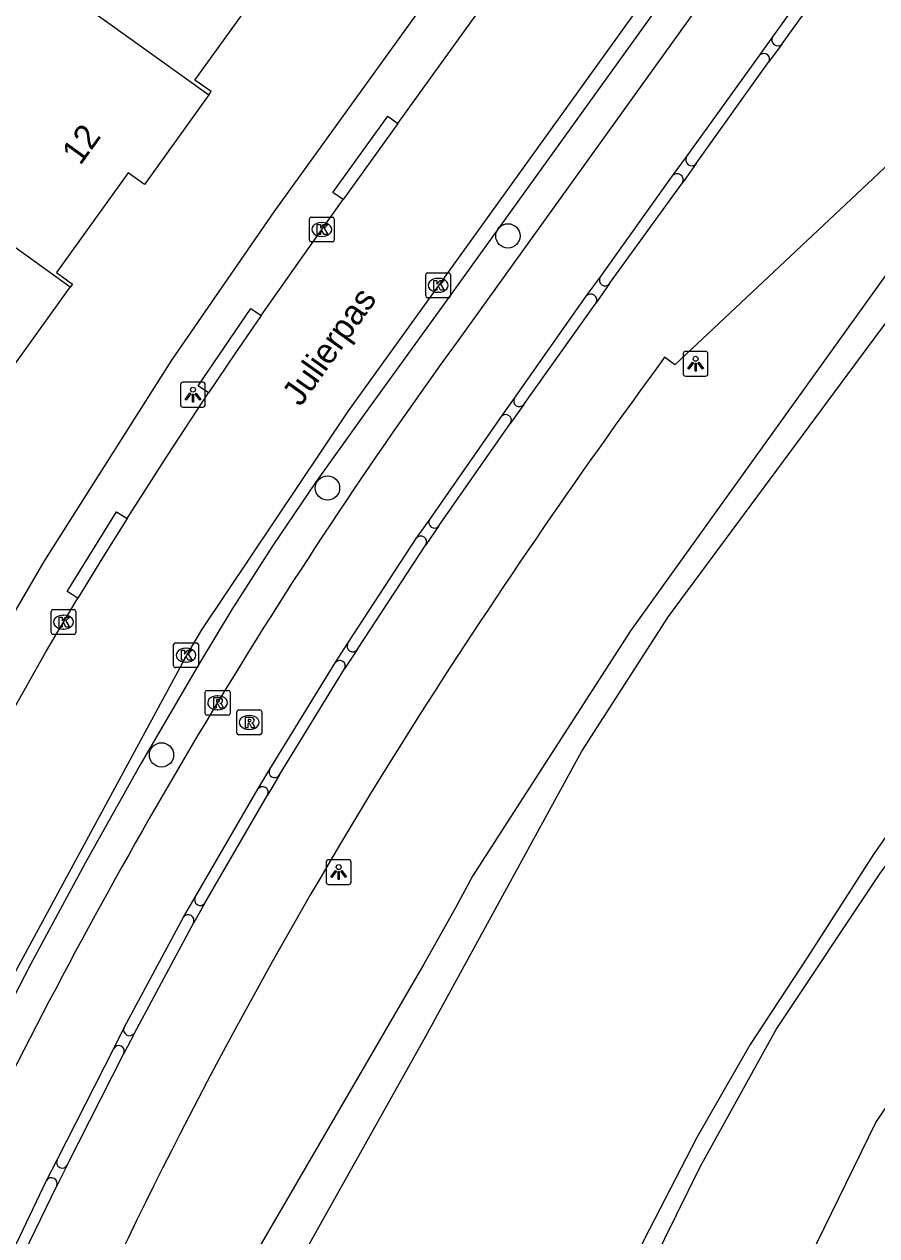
# Model space of a CAD drawing. Extents: x 158838 to 160074, y 386376 to 387776.
# Drawn here: x 159243.35 to 159277.66, y 386797.89 to 386846.63 of the extents above; entities that cross this region are included whole.
import ezdxf

# ---------------------------------------------------------------- set-up
doc = ezdxf.new("R2010")
doc.units = 0
for name, color, linetype in [('IMGEO_Berm_groen', 7, 'Continuous'), ('IMGEO_Boom', 7, 'Continuous'), ('IMGEO_Fietspad_gesloten', 7, 'Continuous'), ('IMGEO_Groenvoorziening', 7, 'Continuous'), ('IMGEO_Haag', 7, 'Continuous'), ('IMGEO_Kolk', 7, 'Continuous'), ('IMGEO_Lichtpunt', 7, 'Continuous'), ('IMGEO_Loofbos', 7, 'Continuous'), ('IMGEO_Openbare_ruimte_label', 7, 'Continuous'), ('IMGEO_OVBaan_gesloten', 7, 'Continuous'), ('IMGEO_Pand', 7, 'Continuous'), ('IMGEO_Pand_nummerreeks', 7, 'Continuous'), ('IMGEO_Rijbaan_lokaal_open', 7, 'Continuous'), ('IMGEO_Rioolput', 7, 'Continuous'), ('IMGEO_Voetpad_open', 7, 'Continuous'), ('IMGEO_Waterloop', 7, 'Continuous')]:
    doc.layers.add(name, color=color, linetype=linetype)

msp = doc.modelspace()

# ---------------------------------------------------------------- linework, layer by layer
at = {"layer": 'IMGEO_Berm_groen'}
msp.add_lwpolyline([(159295.387, 386860.749), (159267.753, 386822.227), (159261.396, 386812.36), (159260.712, 386811.091), (159259.44, 386808.818), (159251.504, 386795.194), (159240.385, 386772.855), (159239.987, 386771.45), (159240.04, 386770.482), (159240.179, 386769.522), (159240.404, 386768.578), (159240.711, 386767.659), (159241.1, 386766.77), (159241.567, 386765.92), (159242.107, 386765.115), (159242.718, 386764.361), (159243.393, 386763.665), (159243.51, 386763.556), (159246.227, 386761.743)], dxfattribs=at)
at = {"layer": 'IMGEO_Boom'}
for centre in [(159262.816, 386838.112), (159255.556, 386827.97), (159248.878, 386817.236)]:
    msp.add_circle(centre, 0.489, dxfattribs=at)
at = {"layer": 'IMGEO_Fietspad_gesloten'}
for points in [[(159289.915, 386874.409), (159260.77, 386833.848)], [(159273.477, 386846.12), (159276.398, 386850.189)], [(159272.946, 386845.362), (159273.477, 386846.12)], [(159270.006, 386841.288), (159272.946, 386845.362)], [(159269.44, 386840.528), (159270.006, 386841.288)], [(159266.538, 386836.462), (159269.44, 386840.528)], [(159265.97, 386835.682), (159266.538, 386836.462)], [(159263.08, 386831.588), (159265.97, 386835.682)], [(159262.563, 386830.847), (159263.08, 386831.588)], [(159259.672, 386826.703), (159262.563, 386830.847)], [(159259.131, 386825.94), (159259.672, 386826.703)], [(159256.371, 386821.725), (159259.131, 386825.94)], [(159255.867, 386820.937), (159256.371, 386821.725)], [(159253.231, 386816.66), (159255.867, 386820.937)], [(159252.754, 386815.852), (159253.231, 386816.66)], [(159250.234, 386811.517), (159252.754, 386815.852)], [(159249.766, 386810.71), (159250.234, 386811.517)], [(159247.374, 386806.27), (159249.766, 386810.71)], [(159246.955, 386805.428), (159247.374, 386806.27)], [(159244.68, 386800.944), (159246.955, 386805.428)], [(159244.248, 386800.111), (159244.68, 386800.944)], [(159242.073, 386795.583), (159244.248, 386800.111)]]:
    msp.add_lwpolyline(points, dxfattribs=at)
for centre, radius, start, end in [((159428.466, 386711.976), 207.304, 143.99241, 148.91485), ((159443.078, 386703.143), 224.378, 148.90963, 153.47047)]:
    msp.add_arc(centre, radius, start, end, dxfattribs=at)
at = {"layer": 'IMGEO_Groenvoorziening'}
msp.add_lwpolyline([(159246.227, 386761.743), (159247.31, 386761.41), (159248.321, 386761.304), (159249.049, 386761.409), (159249.654, 386761.53), (159250.281, 386761.789), (159250.668, 386761.999), (159250.994, 386762.252), (159251.323, 386762.46), (159251.632, 386762.697), (159251.919, 386762.96), (159251.99, 386763.033), (159270.556, 386800.667), (159273.614, 386806.196), (159277.779, 386812.449), (159305.768, 386851.337)], dxfattribs=at)
at = {"layer": 'IMGEO_Haag'}
msp.add_lwpolyline([(159273.392, 386853.651), (159260.53, 386835.762), (159256.863, 386830.685), (159255.079, 386828.194), (159253.364, 386825.663), (159251.714, 386823.086), (159250.404, 386820.929), (159248.07, 386816.93), (159245.802, 386812.886), (159243.604, 386808.803), (159241.476, 386804.683), (159240.155, 386802.033), (159239.189, 386800.003), (159238.681, 386799.182), (159238.109, 386798.417), (159237.471, 386797.706)], dxfattribs=at)
at = {"layer": 'IMGEO_Kolk'}
for p, q in [((159254.827, 386837.945), (159254.827, 386838.797)), ((159254.902, 386838.871), (159255.754, 386838.871)), ((159255.828, 386838.797), (159255.828, 386837.945)), ((159255.315, 386838.651), (159255.34, 386838.651)), ((159255.754, 386837.871), (159254.902, 386837.871)), ((159255.338, 386838.091), (159255.313, 386838.091)), ((159259.511, 386835.698), (159259.511, 386836.55)), ((159259.586, 386836.624), (159260.438, 386836.624)), ((159259.999, 386836.404), (159260.024, 386836.404)), ((159260.512, 386836.55), (159260.512, 386835.698)), ((159260.022, 386835.844), (159259.997, 386835.844)), ((159260.438, 386835.624), (159259.586, 386835.624)), ((159244.434, 386822.153), (159244.434, 386823.005)), ((159244.509, 386823.079), (159245.361, 386823.079)), ((159244.922, 386822.859), (159244.947, 386822.859)), ((159245.435, 386823.005), (159245.435, 386822.153)), ((159244.945, 386822.299), (159244.92, 386822.299)), ((159245.361, 386822.079), (159244.509, 386822.079)), ((159249.363, 386820.819), (159249.363, 386821.671)), ((159249.438, 386821.745), (159250.29, 386821.745)), ((159250.364, 386821.671), (159250.364, 386820.819)), ((159249.851, 386821.525), (159249.876, 386821.525)), ((159250.29, 386820.745), (159249.438, 386820.745)), ((159249.874, 386820.965), (159249.849, 386820.965))]:
    msp.add_line(p, q, dxfattribs=at)
for points in [[(159254.827, 386837.945), (159254.827, 386838.797)], [(159254.902, 386838.871), (159255.754, 386838.871)], [(159255.828, 386838.797), (159255.828, 386837.945)], [(159255.148, 386838.571), (159255.271, 386838.571), (159255.271, 386838.42), (159255.401, 386838.571), (159255.565, 386838.571), (159255.419, 386838.42), (159255.572, 386838.171), (159255.42, 386838.171), (159255.335, 386838.335), (159255.271, 386838.268), (159255.271, 386838.171), (159255.148, 386838.171), (159255.148, 386838.571)], [(159255.754, 386837.871), (159254.902, 386837.871)], [(159259.511, 386835.698), (159259.511, 386836.55)], [(159259.586, 386836.624), (159260.438, 386836.624)], [(159259.832, 386836.324), (159259.955, 386836.324), (159259.955, 386836.173), (159260.085, 386836.324), (159260.249, 386836.324), (159260.103, 386836.173), (159260.256, 386835.924), (159260.104, 386835.924), (159260.019, 386836.088), (159259.955, 386836.021), (159259.955, 386835.924), (159259.832, 386835.924), (159259.832, 386836.324)], [(159260.512, 386836.55), (159260.512, 386835.698)], [(159260.438, 386835.624), (159259.586, 386835.624)], [(159244.434, 386822.153), (159244.434, 386823.005)], [(159244.509, 386823.079), (159245.361, 386823.079)], [(159244.755, 386822.779), (159244.878, 386822.779), (159244.878, 386822.628), (159245.008, 386822.779), (159245.172, 386822.779), (159245.026, 386822.628), (159245.179, 386822.379), (159245.027, 386822.379), (159244.942, 386822.543), (159244.878, 386822.476), (159244.878, 386822.379), (159244.755, 386822.379), (159244.755, 386822.779)], [(159245.435, 386823.005), (159245.435, 386822.153)], [(159245.361, 386822.079), (159244.509, 386822.079)], [(159249.363, 386820.819), (159249.363, 386821.671)], [(159249.438, 386821.745), (159250.29, 386821.745)], [(159250.364, 386821.671), (159250.364, 386820.819)], [(159249.684, 386821.445), (159249.807, 386821.445), (159249.807, 386821.294), (159249.937, 386821.445), (159250.101, 386821.445), (159249.955, 386821.294), (159250.108, 386821.045), (159249.956, 386821.045), (159249.871, 386821.209), (159249.807, 386821.142), (159249.807, 386821.045), (159249.684, 386821.045), (159249.684, 386821.445)], [(159250.29, 386820.745), (159249.438, 386820.745)]]:
    msp.add_lwpolyline(points, dxfattribs=at)
for centre, start, end in [((159254.904, 386838.795), 91.552, 178.448), ((159254.904, 386838.795), 91.552, 178.448), ((159255.752, 386838.795), 1.552, 88.448), ((159255.752, 386838.795), 1.552, 88.448), ((159254.904, 386837.947), 181.552, 268.448), ((159254.904, 386837.947), 181.552, 268.448), ((159255.752, 386837.947), 271.552, 358.448), ((159255.752, 386837.947), 271.552, 358.448), ((159259.588, 386836.548), 91.552, 178.448), ((159259.588, 386836.548), 91.552, 178.448), ((159260.436, 386836.548), 1.552, 88.448), ((159260.436, 386836.548), 1.552, 88.448), ((159259.588, 386835.7), 181.552, 268.448), ((159259.588, 386835.7), 181.552, 268.448), ((159260.436, 386835.7), 271.552, 358.448), ((159260.436, 386835.7), 271.552, 358.448), ((159244.511, 386823.003), 91.552, 178.448), ((159244.511, 386823.003), 91.552, 178.448), ((159245.359, 386823.003), 1.552, 88.448), ((159245.359, 386823.003), 1.552, 88.448), ((159244.511, 386822.155), 181.552, 268.448), ((159244.511, 386822.155), 181.552, 268.448), ((159245.359, 386822.155), 271.552, 358.448), ((159245.359, 386822.155), 271.552, 358.448), ((159249.44, 386821.669), 91.552, 178.448), ((159249.44, 386821.669), 91.552, 178.448), ((159250.288, 386821.669), 1.552, 88.448), ((159250.288, 386821.669), 1.552, 88.448), ((159249.44, 386820.821), 181.552, 268.448), ((159249.44, 386820.821), 181.552, 268.448), ((159250.288, 386820.821), 271.552, 358.448), ((159250.288, 386820.821), 271.552, 358.448)]:
    msp.add_arc(centre, 0.0765, start, end, dxfattribs=at)
for centre, major_axis, ratio, start_param, end_param in [((159255.314, 386838.371), (-0.387, 0.002), 0.722429, 4.712389, 7.853982), ((159255.339, 386838.371), (-0.39, 0.002), 0.717154, 1.570796, 4.712389), ((159259.998, 386836.124), (-0.387, 0.002), 0.722429, 4.712389, 7.853982), ((159260.023, 386836.124), (-0.39, 0.002), 0.717154, 1.570796, 4.712389), ((159244.921, 386822.579), (-0.387, 0.002), 0.722429, 4.712389, 7.853982), ((159244.946, 386822.579), (-0.39, 0.002), 0.717154, 1.570796, 4.712389), ((159249.85, 386821.245), (-0.387, 0.002), 0.722429, 4.712389, 7.853982), ((159249.875, 386821.245), (-0.39, 0.002), 0.717154, 1.570796, 4.712389)]:
    msp.add_ellipse(centre, major_axis=major_axis, ratio=ratio, start_param=start_param, end_param=end_param, dxfattribs=at)
at = {"layer": 'IMGEO_Lichtpunt'}
for p, q in [((159269.871, 386833.372), (159269.871, 386832.565)), ((159269.871, 386833.372), (159269.871, 386832.565)), ((159270.773, 386833.467), (159269.965, 386833.467)), ((159270.773, 386833.467), (159269.965, 386833.467)), ((159270.867, 386832.565), (159270.867, 386833.372)), ((159270.867, 386832.565), (159270.867, 386833.372)), ((159269.965, 386832.471), (159270.773, 386832.471)), ((159269.965, 386832.471), (159270.773, 386832.471)), ((159249.644, 386832.129), (159249.644, 386831.322)), ((159249.644, 386832.129), (159249.644, 386831.322)), ((159250.546, 386832.224), (159249.738, 386832.224)), ((159250.546, 386832.224), (159249.738, 386832.224)), ((159250.64, 386831.322), (159250.64, 386832.129)), ((159250.64, 386831.322), (159250.64, 386832.129)), ((159249.738, 386831.228), (159250.546, 386831.228)), ((159249.738, 386831.228), (159250.546, 386831.228)), ((159255.509, 386812.926), (159255.509, 386812.119)), ((159255.509, 386812.926), (159255.509, 386812.119)), ((159256.411, 386813.021), (159255.603, 386813.021)), ((159256.411, 386813.021), (159255.603, 386813.021)), ((159256.505, 386812.119), (159256.505, 386812.926)), ((159256.505, 386812.119), (159256.505, 386812.926)), ((159255.603, 386812.025), (159256.411, 386812.025)), ((159255.603, 386812.025), (159256.411, 386812.025))]:
    msp.add_line(p, q, dxfattribs=at)
for points in [[(159270.245, 386833.036), (159270.284, 386833.008), (159270.096, 386832.746), (159270.058, 386832.773), (159270.245, 386833.036)], [(159270.347, 386832.988), (159270.394, 386832.988), (159270.394, 386832.666), (159270.347, 386832.666), (159270.347, 386832.988)], [(159270.457, 386833.008), (159270.495, 386833.035), (159270.682, 386832.773), (159270.643, 386832.745), (159270.457, 386833.008)], [(159250.018, 386831.793), (159250.057, 386831.765), (159249.869, 386831.503), (159249.831, 386831.53), (159250.018, 386831.793)], [(159250.12, 386831.745), (159250.167, 386831.745), (159250.167, 386831.423), (159250.12, 386831.423), (159250.12, 386831.745)], [(159250.23, 386831.765), (159250.268, 386831.792), (159250.455, 386831.53), (159250.416, 386831.502), (159250.23, 386831.765)], [(159255.883, 386812.59), (159255.922, 386812.562), (159255.734, 386812.3), (159255.696, 386812.327), (159255.883, 386812.59)], [(159255.985, 386812.542), (159256.032, 386812.542), (159256.032, 386812.22), (159255.985, 386812.22), (159255.985, 386812.542)], [(159256.095, 386812.562), (159256.133, 386812.589), (159256.32, 386812.327), (159256.281, 386812.299), (159256.095, 386812.562)]]:
    msp.add_lwpolyline(points, dxfattribs=at)
for centre in [(159270.37, 386833.17), (159250.143, 386831.927), (159256.008, 386812.724)]:
    msp.add_circle(centre, 0.0994, dxfattribs=at)
for centre, start, end in [((159269.965, 386833.372), 90, 180), ((159269.965, 386833.372), 90, 180), ((159270.773, 386833.372), 0, 90), ((159270.773, 386833.372), 0, 90), ((159269.965, 386832.565), 180, 270), ((159269.965, 386832.565), 180, 270), ((159270.773, 386832.565), 270, 0), ((159270.773, 386832.565), 270, 360), ((159249.738, 386832.129), 90, 180), ((159249.738, 386832.129), 90, 180), ((159250.546, 386832.129), 0, 90), ((159250.546, 386832.129), 0, 90), ((159249.738, 386831.322), 180, 270), ((159249.738, 386831.322), 180, 270), ((159250.546, 386831.322), 270, 0), ((159250.546, 386831.322), 270, 360), ((159255.603, 386812.926), 90, 180), ((159255.603, 386812.926), 90, 180), ((159256.411, 386812.926), 0, 90), ((159256.411, 386812.926), 0, 90), ((159255.603, 386812.119), 180, 270), ((159255.603, 386812.119), 180, 270), ((159256.411, 386812.119), 270, 0), ((159256.411, 386812.119), 270, 360)]:
    msp.add_arc(centre, 0.0946, start, end, dxfattribs=at)
at = {"layer": 'IMGEO_Loofbos'}
msp.add_lwpolyline([(159253.846, 386749.624), (159253.963, 386750), (159257.448, 386761.205), (159277.624, 386802.456), (159300.846, 386836.608), (159308.987, 386845.652), (159313.324, 386845.108), (159309.692, 386855.626)], dxfattribs=at)
at = {"layer": 'IMGEO_OVBaan_gesloten'}
for points in [[(159295.549, 386869.585), (159292.478, 386862.818), (159289.882, 386857.012), (159279.508, 386842.292), (159269.535, 386832.931), (159269.123, 386833.233)], [(159273.85, 386845.844), (159276.783, 386849.924)], [(159273.85, 386845.844), (159273.308, 386845.095)], [(159270.387, 386841.02), (159273.308, 386845.095)], [(159270.387, 386841.02), (159269.839, 386840.252)], [(159266.905, 386836.191), (159269.839, 386840.252)], [(159266.905, 386836.191), (159266.365, 386835.415)], [(159263.456, 386831.331), (159266.365, 386835.415)], [(159263.456, 386831.331), (159262.923, 386830.576)], [(159260.033, 386826.444), (159262.923, 386830.576)], [(159260.033, 386826.444), (159259.51, 386825.68)], [(159256.76, 386821.485), (159259.51, 386825.68)], [(159256.76, 386821.485), (159256.246, 386820.694)], [(159253.627, 386816.43), (159256.246, 386820.694)], [(159253.627, 386816.43), (159253.143, 386815.617)], [(159250.623, 386811.274), (159253.143, 386815.617)], [(159250.623, 386811.274), (159250.159, 386810.469)], [(159247.79, 386806.047), (159250.159, 386810.469)], [(159247.79, 386806.047), (159247.36, 386805.224)], [(159245.086, 386800.74), (159247.36, 386805.224)], [(159245.086, 386800.74), (159244.661, 386799.903)], [(159242.481, 386795.398), (159244.661, 386799.903)]]:
    msp.add_lwpolyline(points, dxfattribs=at)
for centre, radius, start, end in [((159485.462, 386674.364), 268.406, 143.70823, 147.55786), ((159439.59, 386704.553), 213.5, 147.79118, 154.52356)]:
    msp.add_arc(centre, radius, start, end, dxfattribs=at)
at = {"layer": 'IMGEO_Pand'}
for points in [[(159250.785, 386843.792), (159250.873, 386843.914), (159250.224, 386844.381), (159253.121, 386848.404), (159253.77, 386847.937), (159256.368, 386851.544)], [(159244.539, 386848.455), (159244.452, 386848.333), (159250.785, 386843.792)], [(159250.785, 386843.792), (159248.187, 386840.183), (159247.538, 386840.651), (159244.647, 386836.636), (159245.296, 386836.169), (159245.208, 386836.047)], [(159245.208, 386836.047), (159238.885, 386840.592), (159238.973, 386840.714), (159235.399, 386843.28)], [(159239.613, 386828.276), (159239.701, 386828.399), (159239.052, 386828.867), (159241.96, 386832.905), (159242.609, 386832.438), (159245.208, 386836.047)]]:
    msp.add_lwpolyline(points, dxfattribs=at)
at = {"layer": 'IMGEO_Rijbaan_lokaal_open'}
for points in [[(159231.305, 386794.999), (159233.189, 386795.661), (159234.033, 386796.005), (159234.842, 386796.423), (159235.611, 386796.912), (159236.333, 386797.468), (159237.003, 386798.086), (159237.614, 386798.761), (159238.163, 386799.488), (159238.645, 386800.261), (159238.66, 386800.288), (159239.618, 386802.301), (159249.891, 386821.241), (159250.502, 386822.26), (159256.377, 386831.036), (159260.043, 386836.113), (159272.905, 386854.001), (159286.185, 386872.449), (159287.428, 386874.189), (159288.379, 386875.519)], [(159258.389, 386842.63), (159261.71, 386847.24)], [(159258.389, 386842.63), (159256.182, 386839.57)], [(159252.89, 386834.913), (159254.612, 386837.365), (159255.325, 386838.371), (159256.182, 386839.57)], [(159252.89, 386834.913), (159251.827, 386833.362), (159250.77, 386831.801)], [(159247.494, 386826.746), (159249.115, 386829.285), (159250.77, 386831.801)], [(159247.494, 386826.746), (159246.504, 386825.164), (159245.506, 386823.542)], [(159242.728, 386818.731), (159244.208, 386821.349), (159244.932, 386822.579), (159245.506, 386823.542)]]:
    msp.add_lwpolyline(points, dxfattribs=at)
at = {"layer": 'IMGEO_Rioolput'}
for p, q in [((159250.636, 386818.905), (159250.636, 386819.757)), ((159250.711, 386819.831), (159251.563, 386819.831)), ((159251.637, 386819.757), (159251.637, 386818.905)), ((159251.124, 386819.611), (159251.149, 386819.611)), ((159251.563, 386818.831), (159250.711, 386818.831)), ((159251.147, 386819.051), (159251.122, 386819.051)), ((159251.908, 386818.116), (159251.908, 386818.968)), ((159251.983, 386819.042), (159252.835, 386819.042)), ((159252.396, 386818.822), (159252.421, 386818.822)), ((159252.909, 386818.968), (159252.909, 386818.116)), ((159252.419, 386818.262), (159252.394, 386818.262)), ((159252.835, 386818.042), (159251.983, 386818.042))]:
    msp.add_line(p, q, dxfattribs=at)
for points in [[(159250.636, 386818.905), (159250.636, 386819.757)], [(159250.711, 386819.831), (159251.563, 386819.831)], [(159251.637, 386819.757), (159251.637, 386818.905)], [(159251.225, 386819.529), (159250.973, 386819.531), (159250.973, 386819.131)], [(159250.973, 386819.131), (159251.097, 386819.131), (159251.097, 386819.293), (159251.108, 386819.293)], [(159251.151, 386819.45), (159251.097, 386819.45), (159251.097, 386819.369)], [(159251.097, 386819.369), (159251.149, 386819.369)], [(159251.155, 386819.264), (159251.226, 386819.131), (159251.366, 386819.131), (159251.301, 386819.257)], [(159251.563, 386818.831), (159250.711, 386818.831)], [(159251.908, 386818.116), (159251.908, 386818.968)], [(159251.983, 386819.042), (159252.835, 386819.042)], [(159252.497, 386818.74), (159252.245, 386818.742), (159252.245, 386818.342)], [(159252.909, 386818.968), (159252.909, 386818.116)], [(159252.245, 386818.342), (159252.369, 386818.342), (159252.369, 386818.504), (159252.38, 386818.504)], [(159252.423, 386818.661), (159252.369, 386818.661), (159252.369, 386818.58)], [(159252.369, 386818.58), (159252.421, 386818.58)], [(159252.427, 386818.475), (159252.498, 386818.342), (159252.638, 386818.342), (159252.573, 386818.468)], [(159252.835, 386818.042), (159251.983, 386818.042)]]:
    msp.add_lwpolyline(points, dxfattribs=at)
for centre, radius, start, end in [((159250.713, 386819.755), 0.0765, 91.552, 178.448), ((159250.713, 386819.755), 0.0765, 91.552, 178.448), ((159251.561, 386819.755), 0.0765, 1.552, 88.448), ((159251.561, 386819.755), 0.0765, 1.552, 88.448), ((159251.107, 386819.24), 0.0533, 26.0293, 88.6989), ((159251.133, 386819.558), 0.19, 274.7715, 282.9687), ((159251.157, 386819.354), 0.0964, 77.0061, 93.1865), ((159251.171, 386819.411), 0.0378, 276.6634, 79.6772), ((159251.224, 386819.419), 0.109, 350.3612, 89.416), ((159251.222, 386819.419), 0.112, 277.5842, 350.9817), ((159251.206, 386819.204), 0.108, 29.5134, 73.7905), ((159250.713, 386818.907), 0.0765, 181.552, 268.448), ((159250.713, 386818.907), 0.0765, 181.552, 268.448), ((159251.561, 386818.907), 0.0765, 271.552, 358.448), ((159251.561, 386818.907), 0.0765, 271.552, 358.448), ((159251.985, 386818.966), 0.0765, 91.552, 178.448), ((159251.985, 386818.966), 0.0765, 91.552, 178.448), ((159252.496, 386818.63), 0.109, 350.3612, 89.416), ((159252.833, 386818.966), 0.0765, 1.552, 88.448), ((159252.833, 386818.966), 0.0765, 1.552, 88.448), ((159252.379, 386818.451), 0.0533, 26.0293, 88.6989), ((159252.405, 386818.769), 0.19, 274.7715, 282.9687), ((159252.429, 386818.565), 0.0964, 77.0061, 93.1865), ((159252.443, 386818.622), 0.0378, 276.6634, 79.6772), ((159252.494, 386818.63), 0.112, 277.5842, 350.9817), ((159252.478, 386818.415), 0.108, 29.5134, 73.7905), ((159251.985, 386818.118), 0.0765, 181.552, 268.448), ((159251.985, 386818.118), 0.0765, 181.552, 268.448), ((159252.833, 386818.118), 0.0765, 271.552, 358.448), ((159252.833, 386818.118), 0.0765, 271.552, 358.448)]:
    msp.add_arc(centre, radius, start, end, dxfattribs=at)
for centre, major_axis, ratio, start_param, end_param in [((159251.123, 386819.331), (-0.387, 0.002), 0.722429, 4.712389, 7.853982), ((159251.148, 386819.331), (-0.39, 0.002), 0.717154, 1.570796, 4.712389), ((159252.395, 386818.542), (-0.387, 0.002), 0.722429, 4.712389, 7.853982), ((159252.42, 386818.542), (-0.39, 0.002), 0.717154, 1.570796, 4.712389)]:
    msp.add_ellipse(centre, major_axis=major_axis, ratio=ratio, start_param=start_param, end_param=end_param, dxfattribs=at)
at = {"layer": 'IMGEO_Voetpad_open'}
for points in [[(159268.011, 386859.357), (159253.399, 386839.081), (159249.281, 386833.119), (159244.141, 386825.019), (159240.91, 386819.482)], [(159256.182, 386839.57), (159255.777, 386839.862), (159257.984, 386842.922), (159258.389, 386842.63)], [(159250.77, 386831.801), (159250.357, 386832.082), (159252.477, 386835.194), (159252.89, 386834.913)], [(159245.506, 386823.542), (159245.082, 386823.805), (159247.07, 386827.009), (159247.494, 386826.746)]]:
    msp.add_lwpolyline(points, dxfattribs=at)
for centre, radius, start, end in [((159273.67, 386845.99), 0.232, 146.0508, 320.9503), ((159273.122, 386845.222), 0.225, 325.6375, 141.5398), ((159270.206, 386841.168), 0.234, 149.0852, 320.6688), ((159269.628, 386840.374), 0.243, 329.924, 140.7305), ((159266.725, 386836.331), 0.228, 144.8268, 322.2874), ((159266.157, 386835.533), 0.239, 330.4441, 141.4425), ((159263.275, 386831.47), 0.228, 148.9865, 322.3074), ((159262.732, 386830.697), 0.226, 327.5463, 138.5104), ((159259.857, 386826.579), 0.222, 146.2316, 322.4532), ((159259.318, 386825.806), 0.23, 326.8413, 144.2573), ((159256.569, 386821.611), 0.229, 149.9846, 326.669), ((159256.051, 386820.807), 0.225, 329.7857, 144.8815), ((159253.432, 386816.55), 0.229, 151.3293, 328.374), ((159252.947, 386815.731), 0.227, 329.7787, 147.9478), ((159250.436, 386811.407), 0.23, 151.3596, 324.6561), ((159249.954, 386810.575), 0.231, 332.6313, 144.3328), ((159247.591, 386806.176), 0.237, 156.4934, 327.1189), ((159247.155, 386805.321), 0.227, 334.8113, 151.7195), ((159244.885, 386800.845), 0.227, 154.2317, 332.4126), ((159244.449, 386799.996), 0.232, 336.2822, 150.2552)]:
    msp.add_arc(centre, radius, start, end, dxfattribs=at)
at = {"layer": 'IMGEO_Waterloop'}
for points in [[(159243.655, 386775.496), (159247.064, 386783.134), (159253.594, 386795.373), (159259.508, 386805.927), (159265.791, 386817.385), (159269.282, 386822.806), (159277.228, 386833.545), (159284.538, 386843.381), (159289.98, 386850.732), (159295.668, 386859.233)], [(159303.301, 386849.075), (159296.943, 386840.364), (159285.627, 386824.785), (159277.547, 386813.251), (159274.878, 386809.101), (159272.562, 386805.589), (159270.413, 386801.844), (159268.305, 386797.742), (159266.166, 386793.116), (159263.45, 386788.071), (159260.06, 386780.489), (159256.668, 386774.174), (159253.949, 386768.553), (159252.625, 386765.583), (159251.877, 386764.262), (159251.327, 386763.399), (159250.4, 386762.835), (159249.454, 386762.68), (159248.391, 386762.765), (159247.388, 386762.973), (159246.672, 386763.237), (159245.401, 386764.079), (159244.354, 386765.147)]]:
    msp.add_lwpolyline(points, dxfattribs=at)

# ---------------------------------------------------------------- texts
at = {"layer": 'IMGEO_Openbare_ruimte_label'}
msp.add_text('Julierpas', height=1, rotation=54.6089, dxfattribs=at).set_placement((159254.473, 386831.21))
at = {"layer": 'IMGEO_Pand_nummerreeks'}
msp.add_text('12', height=1, rotation=54.2432, dxfattribs=at).set_placement((159245.608, 386840.914))

doc.saveas('drawing.dxf')
